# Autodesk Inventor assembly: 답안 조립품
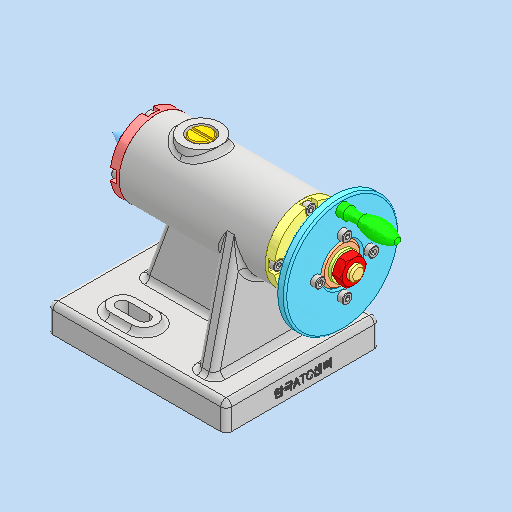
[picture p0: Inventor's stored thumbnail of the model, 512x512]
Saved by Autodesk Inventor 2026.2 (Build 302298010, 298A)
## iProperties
Created: 2026-09
Part Number: 답안 조립품
Document SubType Name: Assembly
Designer: PC-2-06
Author: PC-2-06
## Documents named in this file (18)
- C:\Users\PC-2-06\Desktop\760903V1002\답안 조립품.iam
- C:\Users\PC-2-06\Desktop\760903V1002\1.본체.ipt
- C:\Users\PC-2-06\Desktop\760903V1002\6각 너트 M8\6각 너트 M8.ipt
- C:\Users\PC-2-06\Desktop\760903V1002\가이드 부시\가이드 부시.ipt
- C:\Users\PC-2-06\Desktop\760903V1002\나사축\나사축.ipt
- C:\Users\PC-2-06\Desktop\760903V1002\돌림판\돌림판.ipt
- C:\Users\PC-2-06\Desktop\760903V1002\멈춤나사 M3\멈춤나사 M3.ipt
- C:\Users\PC-2-06\Desktop\760903V1002\부시\부시.ipt
- C:\Users\PC-2-06\Desktop\760903V1002\센터\센터.ipt
- C:\Users\PC-2-06\Desktop\760903V1002\센터홀더\센터홀더.ipt
- C:\Users\PC-2-06\Desktop\760903V1002\스톱퍼\스톱퍼.ipt
- C:\Users\PC-2-06\Desktop\760903V1002\슬리브\슬리브.ipt
- C:\Users\PC-2-06\Desktop\760903V1002\커버\커버.ipt
- C:\Users\PC-2-06\Desktop\760903V1002\평 와셔 M8\평 와셔 M8.ipt
- C:\Users\PC-2-06\Desktop\760903V1002\평행 키 4x4x10\평행 키 4x4x10.ipt
- C:\Users\PC-2-06\Desktop\760903V1002\플랜지\플랜지.ipt
- C:\Users\PC-2-06\Desktop\760903V1002\핸들\핸들.ipt
- C:\Users\PC-2-06\Desktop\760903V1002\6각 구멍붙이 볼트 M3x8\6각 구멍붙이 볼트 M3x8.ipt
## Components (17 placed, 6 different names)
1. 1.본체:1
2. 6각 너트 M8:1
3. 가이드 부시:1
4. 핸들:1
5. 6각 구멍붙이 볼트 M3x8:2
6. 6각 구멍붙이 볼트 M3x8:3
7. 6각 구멍붙이 볼트 M3x8:4
8. 6각 구멍붙이 볼트 M3x8:5
9. 플랜지:2
10. 6각 구멍붙이 볼트 M3x8:1
11. 6각 구멍붙이 볼트 M3x8:6
12. 6각 구멍붙이 볼트 M3x8:7
13. 6각 구멍붙이 볼트 M3x8:8
14. 6각 구멍붙이 볼트 M3x8:9
15. 6각 구멍붙이 볼트 M3x8:10
16. 6각 구멍붙이 볼트 M3x8:11
17. 6각 구멍붙이 볼트 M3x8:12
